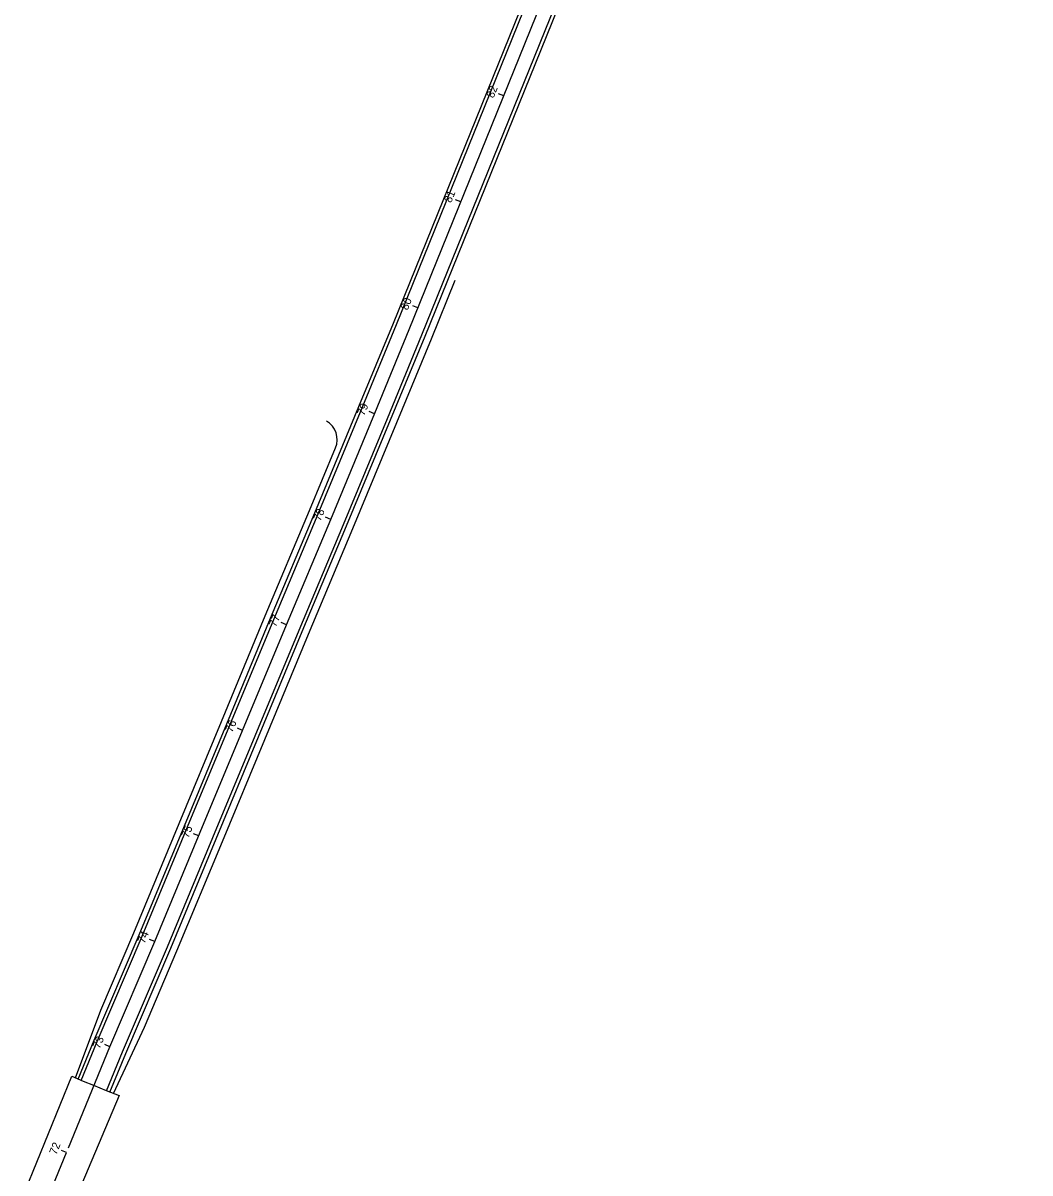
# Model space of a CAD drawing. Extents: x 2318076 to 2324211, y 613525 to 629939.
# Drawn here: x 2318934 to 2319815, y 622014 to 623020 of the extents above; entities that cross this region are included whole.
import ezdxf

# ---------------------------------------------------------------- set-up
doc = ezdxf.new("R2010")
doc.units = 0
for name, color, linetype in [('BR_X_Slab_Object', 7, 'Continuous'), ('GE_P_CL_50', 7, 'Continuous'), ('PV_P_EOP', 7, 'Continuous'), ('PV_P_Shoulder', 7, 'Continuous'), ('RD_X_GR_Lt', 7, 'Continuous'), ('RD_X_GR_Rt', 7, 'Continuous')]:
    doc.layers.add(name, color=color, linetype=linetype)

msp = doc.modelspace()

# ---------------------------------------------------------------- linework, layer by layer
at = {"layer": 'BR_X_Slab_Object'}
msp.add_lwpolyline([(2318975.9, 621982.3), (2318966.6, 621986.3), (2318955.8, 621991.1), (2318945.1, 621995.5), (2318936.1, 621999), (2318976.9, 622099.1), (2318986.6, 622094.8), (2318995.7, 622091.2), (2319006.8, 622086.5), (2319018.1, 622082.3), (2318975.9, 621982.3)], dxfattribs=at)
at = {"layer": 'GE_P_CL_50'}
for p, q in [((2319354.5, 622956.4), (2319349.8, 622958.3)), ((2319317, 622863.7), (2319312.3, 622865.6)), ((2319279.4, 622771), (2319274.8, 622772.9)), ((2319241.4, 622678.5), (2319236.8, 622680.4)), ((2319203.1, 622586.1), (2319198.5, 622588.1)), ((2319164.4, 622493.9), (2319159.8, 622495.8)), ((2319126.1, 622401.5), (2319121.5, 622403.5)), ((2319087.7, 622309.2), (2319083.1, 622311.1)), ((2319049.4, 622216.8), (2319044.8, 622218.8)), ((2319010.1, 622124.9), (2319005.6, 622126.8)), ((2318972.2, 622032.3), (2318967.6, 622034.2))]:
    msp.add_line(p, q, dxfattribs=at)
for points in [[(2318973.8, 622036.6), (2319010.1, 622124.9), (2319049.4, 622216.8), (2319089, 622312.5), (2319126.1, 622401.5), (2319164.4, 622493.9), (2319203.1, 622586.1), (2319241.6, 622679), (2319271.8, 622752.1), (2319455.4, 623205.9), (2319483.2, 623276), (2319511.3, 623345.5), (2319540.9, 623420.3), (2319577.1, 623513.5), (2319614.3, 623606.3), (2319629, 623643.1), (2319652.5, 623700.6), (2319689.4, 623792.6), (2319700.1, 623819.1), (2319726.9, 623884.4), (2319763, 623976.2), (2319763, 623976.2), (2319800.6, 624070.3)], [(2318934.1, 621939.9), (2318972.1, 622032.4)]]:
    msp.add_lwpolyline(points, dxfattribs=at)
at = {"layer": 'PV_P_EOP'}
for points in [[(2318985, 622095.4), (2318999, 622129.5), (2319038.3, 622221.5), (2319077.9, 622317.1), (2319115, 622406.2), (2319153.3, 622498.5), (2319192, 622590.8), (2319230.5, 622683.5), (2319260.7, 622756.6), (2319444.3, 623210.4), (2319472.1, 623280.5), (2319500.1, 623349.9), (2319529.8, 623424.7), (2319566, 623517.9), (2319603.2, 623610.8), (2319617.9, 623647.6), (2319641.4, 623705.1), (2319678.2, 623797), (2319689, 623823.7), (2319715.8, 623888.9), (2319751.9, 623980.7), (2319789.4, 624074.7)], [(2319007.2, 622086.4), (2319021.1, 622120.3), (2319060.4, 622212.2), (2319100.1, 622307.9), (2319137.2, 622396.9), (2319175.5, 622489.3), (2319214.2, 622581.5), (2319252.7, 622674.4), (2319282.9, 622747.5), (2319466.6, 623201.5), (2319494.4, 623271.6), (2319522.4, 623341), (2319552.1, 623415.9), (2319588.3, 623509.1), (2319625.5, 623601.9), (2319640.1, 623638.6), (2319663.6, 623696.1), (2319700.5, 623788.1), (2319711.2, 623814.6), (2319738, 623879.9), (2319774.2, 623971.8), (2319811.7, 624065.9)]]:
    msp.add_lwpolyline(points, dxfattribs=at)
at = {"layer": 'PV_P_Shoulder'}
for points in [[(2318982.2, 622096.6), (2318996.2, 622130.7), (2319035.6, 622222.7), (2319075.2, 622318.2), (2319112.2, 622407.3), (2319150.5, 622499.7), (2319189.2, 622591.9), (2319227.7, 622684.7), (2319257.9, 622757.8), (2319441.5, 623211.5), (2319469.3, 623281.6), (2319497.3, 623351.1), (2319527, 623425.8), (2319563.2, 623519), (2319600.4, 623611.9), (2319615.1, 623648.7), (2319638.6, 623706.2), (2319675.5, 623798.2), (2319686.2, 623824.8), (2319713, 623890), (2319749.1, 623981.8), (2319786.6, 624075.9)], [(2319010, 622085.2), (2319023.9, 622119.1), (2319063.2, 622211), (2319102.9, 622306.7), (2319139.9, 622395.8), (2319178.2, 622488.1), (2319216.9, 622580.4), (2319255.5, 622673.2), (2319285.7, 622746.4), (2319469.4, 623200.3), (2319497.2, 623270.4), (2319525.2, 623339.9), (2319554.9, 623414.8), (2319591.1, 623508), (2319628.3, 623600.8), (2319642.9, 623637.4), (2319666.4, 623694.9), (2319703.3, 623787), (2319714, 623813.5), (2319740.8, 623878.8), (2319777, 623970.7), (2319814.5, 624064.8)]]:
    msp.add_lwpolyline(points, dxfattribs=at)
at = {"layer": 'RD_X_GR_Lt'}
msp.add_line((2318980.1, 622097.7), (2319002, 622156.8), dxfattribs=at)
msp.add_lwpolyline([(2319002, 622156.8), (2319031, 622224.6), (2319070.5, 622320.2), (2319107.6, 622409.2), (2319145.9, 622501.6), (2319184.6, 622593.8), (2319207.4, 622648.6)], dxfattribs=at)
msp.add_arc((2319190.1, 622655.8), 18.7, 337.427, 60.4986, dxfattribs=at)
at = {"layer": 'RD_X_GR_Rt'}
msp.add_line((2319013.3, 622084.1), (2319040.3, 622142.1), dxfattribs=at)
msp.add_lwpolyline([(2319040.3, 622142.1), (2319068.7, 622208.7), (2319108.4, 622304.4), (2319145.5, 622393.5), (2319183.8, 622485.8), (2319222.5, 622578), (2319261, 622670.9), (2319291.2, 622744.1), (2319311.9, 622795.3)], dxfattribs=at)

# ---------------------------------------------------------------- texts
at = {"layer": 'GE_P_CL_50'}
for s, rotation, p in [('82', 67.8067, (2319345.4, 622954)), ('81', 67.3882, (2319308.3, 622862.4)), ('80', 67.3882, (2319270.3, 622768.5)), ('79', 67.4813, (2319232.3, 622676.2)), ('78', 67.1236, (2319194, 622584)), ('77', 67.5842, (2319155.2, 622491.4)), ('76', 67.4396, (2319117, 622399.2)), ('75', 67.6176, (2319078.6, 622306.9)), ('74', 67.024, (2319040.3, 622214.6)), ('73', 66.7314, (2319001, 622122.6)), ('72', 68.2796, (2318963.2, 622029.9))]:
    msp.add_text(s, height=7, rotation=rotation, dxfattribs=at).set_placement(p)

doc.saveas('drawing.dxf')
